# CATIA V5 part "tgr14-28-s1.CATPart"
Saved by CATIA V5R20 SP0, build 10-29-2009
Part number: TGR14-28-S1
Revision: 1
Definition: design
Nomenclature: TGR14-28-S1
Source: made
Description: NOT SPECIFIED
Bounding box of the stored display mesh (mm): x -22 to 0.8, y 0 to 14, z -7 to 7
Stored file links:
  C:\Users\Raffaele\Desktop\3D X SITO CF\I-MOLD\TGR-S1\tgr14-s1.step\tgr14-28-s1.CATPart
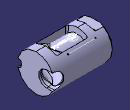
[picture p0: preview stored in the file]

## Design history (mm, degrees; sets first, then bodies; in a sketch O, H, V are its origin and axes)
Set1
  Line1 "LINE #4407": stored without definition
  DatumCurve1 "COMPOSITE_CURVE #4460"
  DatumCurve2 "COMPOSITE_CURVE #4511"
  DatumCurve3 "COMPOSITE_CURVE #4590"
  DatumCurve4 "COMPOSITE_CURVE #4633"
  DatumCurve5 "COMPOSITE_CURVE #4862"
  DatumCurve6 "COMPOSITE_CURVE #5003"
  DatumCurve7 "COMPOSITE_CURVE #5030"
  DatumCurve8 "COMPOSITE_CURVE #5088"
  DatumCurve9 "COMPOSITE_CURVE #5143"
  DatumCurve10 "COMPOSITE_CURVE #5172"
  DatumSurface1 "OPEN_SHELL #4397"
Body1 "MANIFOLD_SOLID_BREP #4398" (main body)
  Solid1: solid without history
